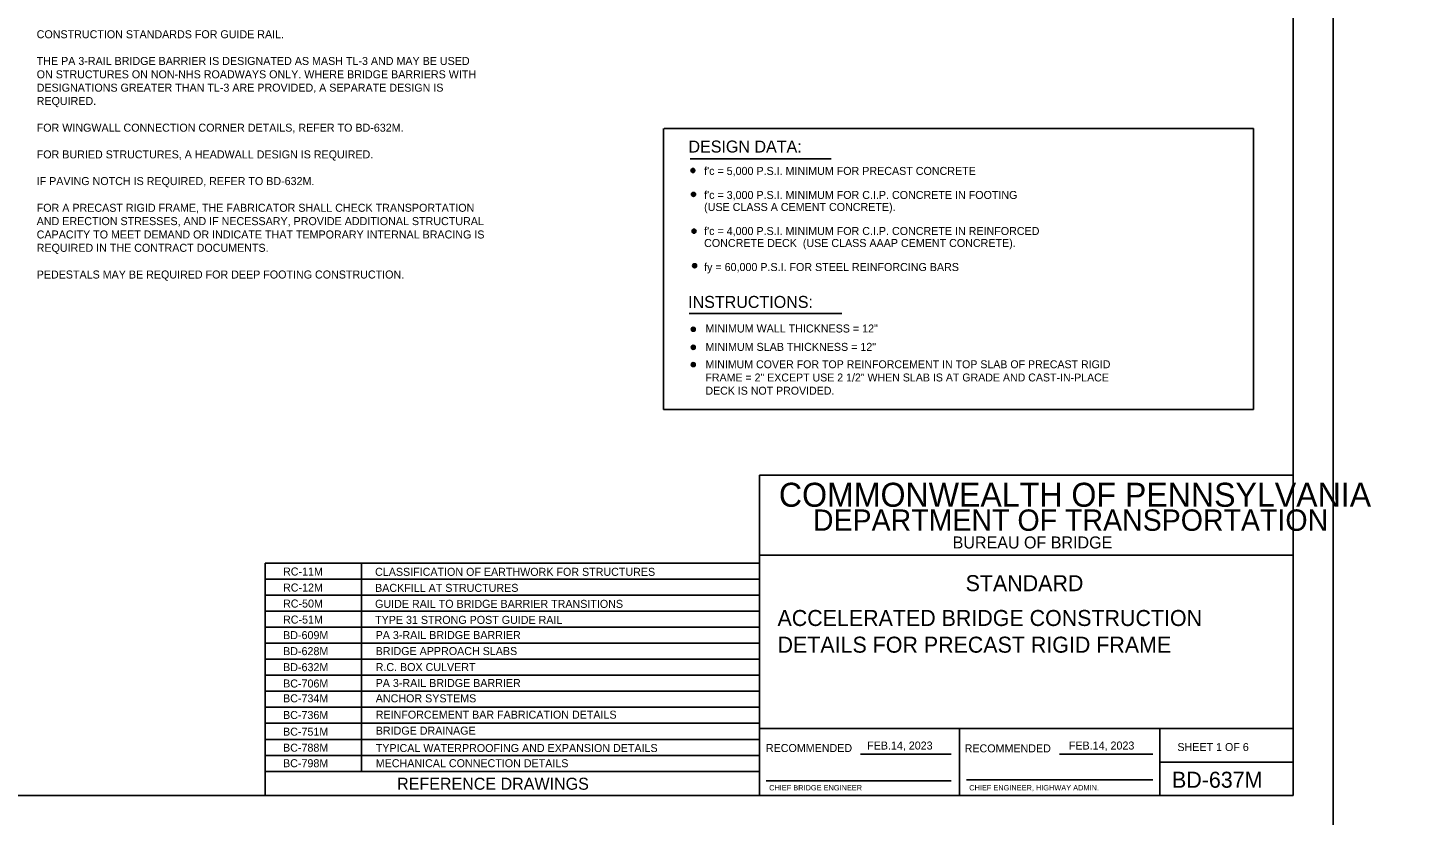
# Model space of a CAD drawing. Extents: x 641328 to 643024, y 298283 to 300065.
# Drawn here: x 641679 to 642196, y 299479 to 299774 of the extents above; entities that cross this region are included whole.
import ezdxf

# ---------------------------------------------------------------- set-up
doc = ezdxf.new("R2010")
doc.units = 0
for name, color, linetype in [('2', 7, 'Continuous'), ('DATES', 7, 'Continuous'), ('PLT-BNDY', 7, 'Continuous'), ('SIGNATORY TITLES', 7, 'Continuous')]:
    doc.layers.add(name, color=color, linetype=linetype)

msp = doc.modelspace()

# ---------------------------------------------------------------- linework, layer by layer
at = {"layer": '2'}
for p, q in [((642153.5, 300050.3), (642153.5, 299486.3)), ((641917.53, 299736.12), (641917.53, 299630.92)), ((642138.68, 299736.12), (641917.75, 299736.12)), ((642138.68, 299630.92), (642138.68, 299736.12)), ((641927.47, 299724.74), (641980.35, 299724.74)), ((641927.1, 299666.78), (641984.35, 299666.78)), ((641917.53, 299630.92), (642138.68, 299630.92)), ((642153.5, 299606.3), (641953.5, 299606.3)), ((641953.5, 299606.3), (641953.5, 299486.3)), ((642153.5, 299486.3), (642153.5, 299606.3)), ((642153.5, 299576.3), (641953.5, 299576.3)), ((641768.13, 299573.3), (641953.5, 299573.3)), ((641768.13, 299573.3), (641768.13, 299486.3)), ((641804.25, 299573.3), (641804.25, 299495.3)), ((641768.13, 299567.3), (641953.5, 299567.3)), ((641768.13, 299561.3), (641953.5, 299561.3)), ((641768.13, 299555.3), (641953.5, 299555.3)), ((641768.13, 299549.3), (641953.5, 299549.3)), ((641768.13, 299543.3), (641953.5, 299543.3)), ((641768.13, 299537.3), (641953.5, 299537.3)), ((641768.13, 299531.3), (641953.5, 299531.3)), ((641768.13, 299525.3), (641953.5, 299525.3)), ((641768.13, 299519.3), (641953.5, 299519.3)), ((641768.13, 299513.3), (641953.5, 299513.3)), ((642153.5, 299511.3), (641953.5, 299511.3)), ((642028.5, 299486.3), (642028.5, 299511.3)), ((642103.5, 299511.3), (642103.5, 299486.3)), ((641768.13, 299507.3), (641953.5, 299507.3)), ((641768.13, 299501.3), (641953.5, 299501.3)), ((641991.35, 299501.8), (642025.39, 299501.8)), ((642065.95, 299501.8), (642100.92, 299501.8)), ((642103.5, 299498.8), (642153.5, 299498.8)), ((641768.13, 299495.3), (641953.5, 299495.3)), ((641956, 299491.8), (642025.39, 299491.8)), ((642031.13, 299492.17), (642100.92, 299492.17)), ((642153.5, 299486.3), (641367.51, 299486.3)), ((641953.5, 299486.3), (642153.5, 299486.3))]:
    msp.add_line(p, q, dxfattribs=at)
for centre, radius in [((641928.51, 299720.38), 0.763), ((641928.51, 299720.38), 0.545), ((641928.51, 299720.38), 0.298), ((641928.51, 299720.38), 0.15), ((641928.51, 299720.38), 0.0644), ((641928.73, 299711.45), 0.763), ((641928.73, 299711.45), 0.545), ((641928.73, 299711.45), 0.298), ((641928.73, 299711.45), 0.15), ((641928.73, 299711.45), 0.0644), ((641928.95, 299697.67), 0.763), ((641928.95, 299697.67), 0.545), ((641928.95, 299697.67), 0.298), ((641928.95, 299697.67), 0.15), ((641928.95, 299697.67), 0.0644), ((641929.16, 299684.71), 0.763), ((641929.16, 299684.71), 0.545), ((641929.16, 299684.71), 0.298), ((641929.16, 299684.71), 0.15), ((641929.16, 299684.71), 0.0644), ((641928.65, 299660.93), 0.763), ((641928.65, 299660.93), 0.545), ((641928.65, 299660.93), 0.298), ((641928.65, 299660.93), 0.15), ((641928.65, 299660.93), 0.0644), ((641928.65, 299654.14), 0.763), ((641928.65, 299654.14), 0.545), ((641928.65, 299654.14), 0.298), ((641928.65, 299654.14), 0.15), ((641928.65, 299654.14), 0.0644), ((641928.65, 299647.68), 0.763), ((641928.65, 299647.68), 0.545), ((641928.65, 299647.68), 0.298), ((641928.65, 299647.68), 0.15), ((641928.65, 299647.68), 0.0644)]:
    msp.add_circle(centre, radius, dxfattribs=at)
at = {"layer": 'PLT-BNDY'}
for points in [[(641327.51, 300065.3), (642168.51, 300065.3), (642168.51, 299471.3), (641327.51, 299471.3)], [(642168.51, 300065.3), (643009.51, 300065.3), (643009.51, 299471.3), (642168.51, 299471.3)]]:
    msp.add_lwpolyline(points, close=True, dxfattribs=at)

# ---------------------------------------------------------------- texts
at = {"layer": '2'}
for s, height, p in [('CONSTRUCTION STANDARDS FOR GUIDE RAIL.', 3, (641682.53, 299769.93)), ('THE PA 3-RAIL BRIDGE BARRIER IS DESIGNATED AS MASH TL-3 AND MAY BE USED', 3, (641682.53, 299759.93)), ('ON STRUCTURES ON NON-NHS ROADWAYS ONLY. WHERE BRIDGE BARRIERS WITH', 3, (641682.53, 299754.93)), ('DESIGNATIONS GREATER THAN TL-3 ARE PROVIDED, A SEPARATE DESIGN IS', 3, (641682.53, 299749.93)), ('REQUIRED.', 3, (641682.53, 299744.93)), ('FOR WINGWALL CONNECTION CORNER DETAILS, REFER TO BD-632M.', 3, (641682.53, 299734.93)), ('DESIGN DATA:', 4.5, (641926.85, 299727.11)), ('FOR BURIED STRUCTURES, A HEADWALL DESIGN IS REQUIRED.  ', 3, (641682.53, 299724.93)), ("f'c = 5,000 P.S.I. MINIMUM FOR PRECAST CONCRETE", 3, (641932.72, 299718.73)), ('IF PAVING NOTCH IS REQUIRED, REFER TO BD-632M.', 3, (641682.53, 299714.93)), ("f'c = 3,000 P.S.I. MINIMUM FOR C.I.P. CONCRETE IN FOOTING ", 3, (641932.72, 299709.73)), ('FOR A PRECAST RIGID FRAME, THE FABRICATOR SHALL CHECK TRANSPORTATION ', 3, (641682.53, 299704.93)), ('(USE CLASS A CEMENT CONCRETE).', 3, (641932.72, 299705.23)), ('AND ERECTION STRESSES, AND IF NECESSARY, PROVIDE ADDITIONAL STRUCTURAL ', 3, (641682.53, 299699.93)), ('CAPACITY TO MEET DEMAND OR INDICATE THAT TEMPORARY INTERNAL BRACING IS ', 3, (641682.53, 299694.93)), ("f'c = 4,000 P.S.I. MINIMUM FOR C.I.P. CONCRETE IN REINFORCED ", 3, (641932.72, 299696.23)), ('CONCRETE DECK  (USE CLASS AAAP CEMENT CONCRETE).', 3, (641932.72, 299691.73)), ('REQUIRED IN THE CONTRACT DOCUMENTS. ', 3, (641682.53, 299689.93)), ('fy = 60,000 P.S.I. FOR STEEL REINFORCING BARS', 3, (641932.72, 299682.73)), ('PEDESTALS MAY BE REQUIRED FOR DEEP FOOTING CONSTRUCTION.  ', 3, (641682.53, 299679.93)), ('INSTRUCTIONS:', 4.5, (641926.72, 299668.91)), ('MINIMUM WALL THICKNESS = 12"', 3, (641933.22, 299659.71)), ('MINIMUM SLAB THICKNESS = 12"', 3, (641933.22, 299652.82)), ('MINIMUM COVER FOR TOP REINFORCEMENT IN TOP SLAB OF PRECAST RIGID', 2.97, (641933.22, 299646.32)), ('FRAME = 2" EXCEPT USE 2 1/2" WHEN SLAB IS AT GRADE AND CAST-IN-PLACE ', 2.97, (641933.22, 299641.37)), ('DECK IS NOT PROVIDED. ', 2.97, (641933.22, 299636.42)), ('COMMONWEALTH OF PENNSYLVANIA', 9, (641960.75, 299594.42)), ('DEPARTMENT OF TRANSPORTATION', 8.0002, (641973.5, 299585.42)), ('BUREAU OF BRIDGE', 4.5, (642025.88, 299578.8)), ('RC-11M', 3, (641774.88, 299568.67)), ('CLASSIFICATION OF EARTHWORK FOR STRUCTURES', 3, (641809.38, 299568.55)), ('RC-12M', 3, (641774.88, 299562.67)), ('BACKFILL AT STRUCTURES', 3, (641809.38, 299562.55)), ('STANDARD', 6, (642030.75, 299562.8)), ('RC-50M', 3, (641774.88, 299556.67)), ('GUIDE RAIL TO BRIDGE BARRIER TRANSITIONS', 3, (641809.38, 299556.55)), ('ACCELERATED BRIDGE CONSTRUCTION', 6, (641960.23, 299549.76)), ('RC-51M', 3, (641774.88, 299550.67)), ('TYPE 31 STRONG POST GUIDE RAIL', 3, (641809.38, 299550.55)), ('PA 3-RAIL BRIDGE BARRIER', 3, (641809.59, 299544.88)), ('DETAILS FOR PRECAST RIGID FRAME', 6, (641960.25, 299539.76)), ('BC-706M', 3, (641774.9, 299526.72)), ('PA 3-RAIL BRIDGE BARRIER', 3, (641809.59, 299526.91)), ('BC-734M', 3, (641774.88, 299521.17)), ('ANCHOR SYSTEMS', 3, (641809.63, 299521.17)), ('BC-736M', 3, (641774.88, 299514.92)), ('REINFORCEMENT BAR FABRICATION DETAILS', 3, (641809.63, 299515.05)), ('BC-788M', 3, (641774.88, 299502.67)), ('TYPICAL WATERPROOFING AND EXPANSION DETAILS', 3, (641809.63, 299502.55)), ('SHEET 1 OF 6', 3, (642110.14, 299502.92)), ('BC-798M', 3, (641774.88, 299496.85)), ('MECHANICAL CONNECTION DETAILS', 3, (641809.63, 299496.85)), ('BD-637M', 6, (642108.13, 299489.17)), ('REFERENCE DRAWINGS', 4.5, (641817.63, 299488.42))]:
    msp.add_text(s, height=height, dxfattribs=at).set_placement(p)
for s, p in [('BD-609M', (641774.9, 299544.84)), ('BD-628M', (641774.9, 299538.84)), ('BRIDGE APPROACH SLABS', (641809.59, 299538.88)), ('BD-632M', (641774.9, 299532.84)), ('R.C. BOX CULVERT', (641809.59, 299532.88)), ('BC-751M', (641774.88, 299508.67)), ('BRIDGE DRAINAGE', (641809.63, 299509.05)), ('RECOMMENDED', (641955.88, 299502.55)), ('RECOMMENDED', (642030.39, 299502.42))]:
    msp.add_text(s, height=3, rotation=360, dxfattribs=at).set_placement(p)
at = {"layer": 'DATES'}
for p in [(641993.84, 299503.48), (642069.46, 299503.48)]:
    msp.add_text('FEB.14, 2023', height=3, dxfattribs=at).set_placement(p)
at = {"layer": 'SIGNATORY TITLES'}
for s, p in [('CHIEF BRIDGE ENGINEER', (641957.1, 299488.17)), ('CHIEF ENGINEER, HIGHWAY ADMIN.', (642032.1, 299488.17))]:
    msp.add_text(s, height=2, dxfattribs=at).set_placement(p)

doc.saveas('drawing.dxf')
